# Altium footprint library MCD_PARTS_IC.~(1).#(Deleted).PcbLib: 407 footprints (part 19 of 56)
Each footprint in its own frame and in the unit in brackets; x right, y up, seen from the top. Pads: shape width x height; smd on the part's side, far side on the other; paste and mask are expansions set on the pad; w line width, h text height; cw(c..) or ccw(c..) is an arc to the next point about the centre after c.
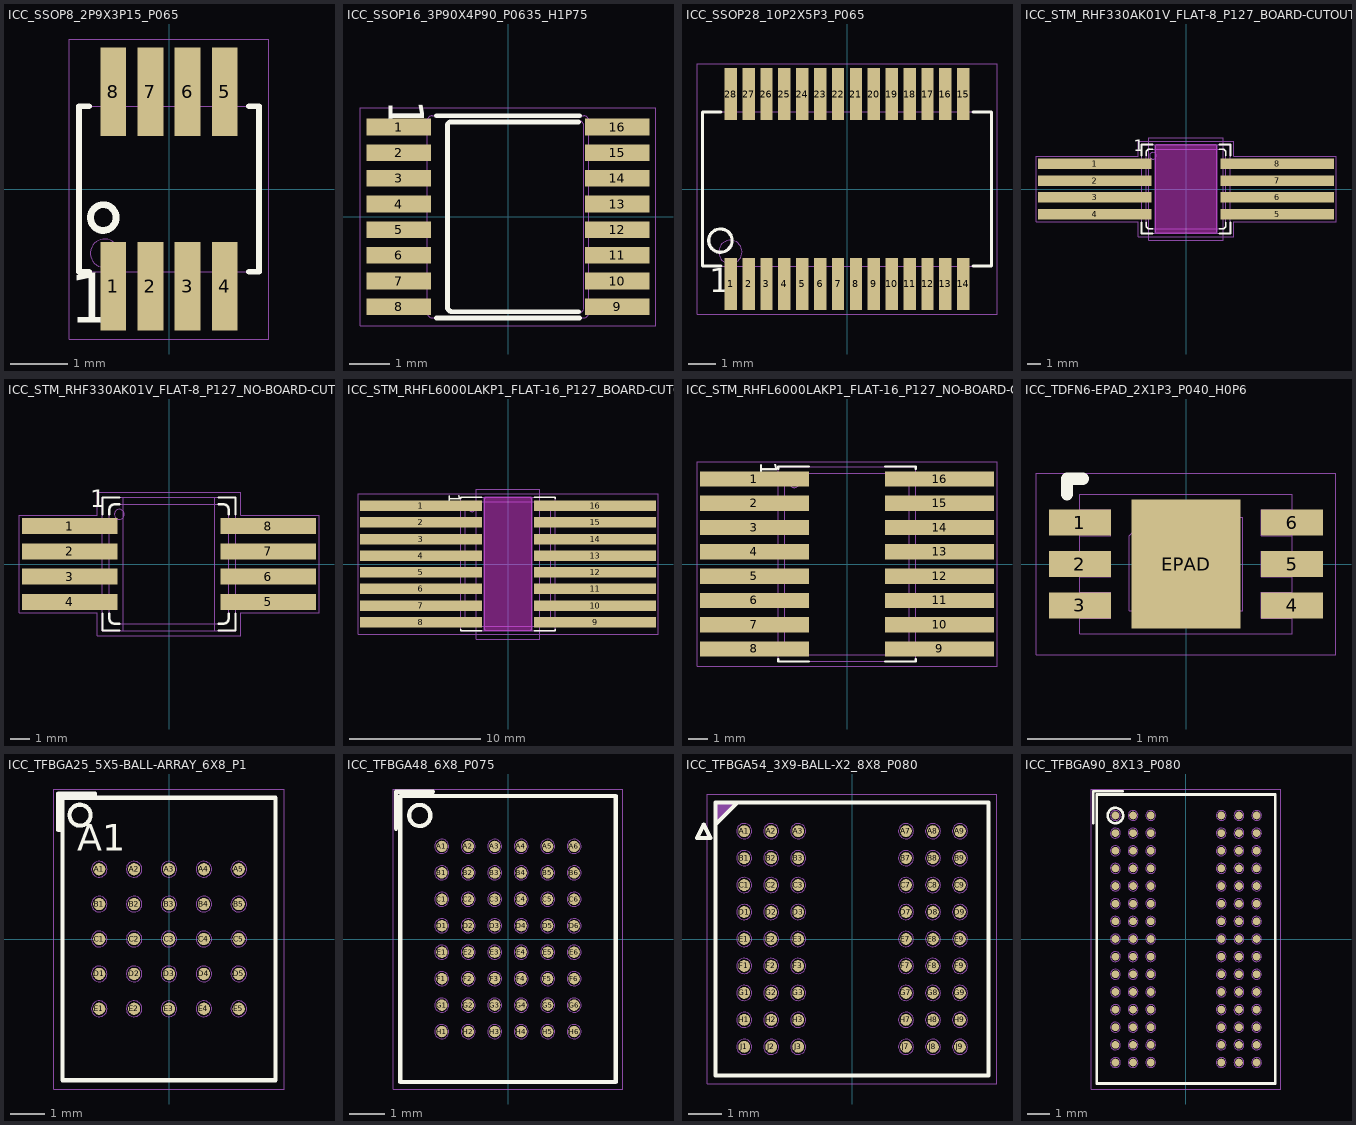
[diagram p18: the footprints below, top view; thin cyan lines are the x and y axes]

## ICC_SSOP8_2P9X3P15_P065 [mm] "MCD-02193"
height 1.3
pads (8):
  rect 0.45x1.55 smd mask+0.05: 1(-0.975,-1.7) 2(-0.325,-1.7) 3(0.325,-1.7) 4(0.975,-1.7) 5(0.975,1.7) 6(0.325,1.7) 7(-0.325,1.7) 8(-0.975,1.7)
Top Overlay:
  circle w0.12: c-1.15,-0.5 r0.225
  lines w0.1: -1.4,-1.45 -1.575,-1.45 -1.575,1.45 -1.4,1.45 ; 1.4,-1.45 1.575,-1.45 1.575,1.45 1.4,1.45
  text "1" at -1.75,-2.625 h1.5
M14-Top Assembly:
  circle w0.01: c-1.125,-1.125 r0.25
  lines w0.01: -1.125,-1.45 -1.125,-2.125 -0.825,-2.125 -0.825,-1.45 ; -1.125,1.45 -1.125,2.125 -0.825,2.125 -0.825,1.45 ; -0.475,-1.45 -0.475,-2.125 -0.175,-2.125 -0.175,-1.45 ; -0.475,1.45 -0.475,2.125 -0.175,2.125 -0.175,1.45 ; 0.175,-1.45 0.175,-2.125 0.475,-2.125 0.475,-1.45 ; 0.175,1.45 0.175,2.125 0.475,2.125 0.475,1.45 ; 0.825,-1.45 0.825,-2.125 1.125,-2.125 1.125,-1.45 ; 0.825,1.45 0.825,2.125 1.125,2.125 1.125,1.45 ; -1.575,-1.45 -1.575,1.45 1.575,1.45 1.575,-1.45 -1.575,-1.45
  text "1" at -1.1,-2.4 h1
  text "4" at 0.75,-2.375 h1
  text "8" at -1.2,1.725 h1
  text "5" at 0.775,1.725 h1
  text "'.Designator'" at -2,-0.5 h0.75
M16-Top Courtyard:
  lines w0.01: -1.75,-2.625 -1.75,2.625 1.75,2.625 1.75,-2.625 -1.75,-2.625
3D body: height 1.11, standoff 1.1, extent -1.373,-1.374 -0.875,-0.875
3D body: height 1.1, standoff 0, extent -1.575,-1.45 1.575,1.45
3D body "User Library-SSOP-8-1.STEP": height 1.28, standoff -0.02, extent -1.587,-2.173 1.563,2.077

## ICC_SSOP16_3P90X4P90_P0635_H1P75 [mm]
height 1.75
pads (16):
  rect 1.6x0.41 smd mask+0.05: 1(-2.7,2.222) 2(-2.7,1.587) 3(-2.7,0.953) 4(-2.7,0.318) 5(-2.7,-0.318) 6(-2.7,-0.953) 7(-2.7,-1.587) 8(-2.7,-2.222) 9(2.7,-2.222) 10(2.7,-1.587) 11(2.7,-0.953) 12(2.7,-0.318) 13(2.7,0.318) 14(2.7,0.953) 15(2.7,1.587) 16(2.7,2.222)
Top Overlay:
  lines w0.12: -1.775,-2.5 1.775,-2.5 ; -1.775,2.5 1.775,2.5 ; 1.75,-2.35 -1.375,-2.35 cw(c-1.375,-2.225) -1.5,-2.225 -1.5,2.25 cw(c-1.4,2.25) -1.4,2.35 1.75,2.35
  text "1" at -3.25,2.9 h1.5
M14-Top Assembly:
  lines w0.01: -2,-2.372 -3.1,-2.372 -3.1,-2.073 -2,-2.073 ; -2,-1.737 -3.1,-1.737 -3.1,-1.438 -2,-1.438 ; -2,-1.102 -3.1,-1.102 -3.1,-0.803 -2,-0.803 ; -2,-0.467 -3.1,-0.467 -3.1,-0.168 -2,-0.168 ; -2,0.168 -3.1,0.168 -3.1,0.467 -2,0.467 ; -2,0.803 -3.1,0.803 -3.1,1.102 -2,1.102 ; -2,1.438 -3.1,1.438 -3.1,1.737 -2,1.737 ; -2,2.073 -3.1,2.073 -3.1,2.372 -2,2.372 ; 2,-2.372 3.1,-2.372 3.1,-2.073 2,-2.073 ; 2,-1.737 3.1,-1.737 3.1,-1.438 2,-1.438 ; 2,-1.102 3.1,-1.102 3.1,-0.803 2,-0.803 ; 2,-0.467 3.1,-0.467 3.1,-0.168 2,-0.168 ; 2,0.168 3.1,0.168 3.1,0.467 2,0.467 ; 2,0.803 3.1,0.803 3.1,1.102 2,1.102 ; 2,1.438 3.1,1.438 3.1,1.737 2,1.737 ; 2,2.073 3.1,2.073 3.1,2.372 2,2.372 ; -2,-2.375 ccw(c-1.875,-2.375) -1.875,-2.5 1.875,-2.5 ccw(c1.875,-2.375) 2,-2.375 2,2.375 ccw(c1.875,2.375) 1.875,2.5 -1.875,2.5 ccw(c-1.875,2.375) -2,2.375 -2,-2.375 ; -1.5,-2.25 ccw(c-1.375,-2.25) -1.375,-2.375 1.75,-2.375 ccw(c1.75,-2.25) 1.875,-2.25 1.875,2.25 ccw(c1.75,2.25) 1.75,2.375 -1.375,2.375 ccw(c-1.375,2.25) -1.5,2.25 -1.5,-2.25
  text "'.Designator'" at -2,-0.5 h0.75
  text "1" at -2.65,2 h0.75
  text "8" at -2.675,-2.475 h0.75
  text "9" at 2.375,-2.475 h0.75
  text "16" at 2.225,2 h0.75
M16-Top Courtyard:
  lines w0.01: -3.65,-2.7 -3.65,2.7 3.65,2.7 3.65,-2.7 -3.65,-2.7
3D body: height 1.75, standoff 0, extent -2,-2.5 2,2.5
3D body "SSOP16_5X4_P0635.STEP": height 1.1, standoff 0, extent -2.997,-2.538 2.997,2.44
3D body: height 1.11, standoff 1.1, extent -1.323,1.801 -0.925,2.2

## ICC_SSOP28_10P2X5P3_P065 [mm]
height 2
pads (28):
  rect 0.45x1.9 smd mask+0.05: 1(-4.225,-3.45) 2(-3.575,-3.45) 3(-2.925,-3.45) 4(-2.275,-3.45) 5(-1.625,-3.45) 6(-0.975,-3.45) 7(-0.325,-3.45) 8(0.325,-3.45) 9(0.975,-3.45) 10(1.625,-3.45) 11(2.275,-3.45) 12(2.925,-3.45) 13(3.575,-3.45) 14(4.225,-3.45) 15(4.225,3.45) 16(3.575,3.45) 17(2.925,3.45) 18(2.275,3.45) 19(1.625,3.45) 20(0.975,3.45) 21(0.325,3.45) 22(-0.325,3.45) 23(-0.975,3.45) 24(-1.625,3.45) 25(-2.275,3.45) 26(-2.925,3.45) 27(-3.575,3.45) 28(-4.225,3.45)
Top Overlay:
  circle w0.12: c-4.6,-1.875 r0.425
  lines w0.12: -4.575,-2.8 -5.25,-2.8 -5.25,2.8 -4.575,2.8 ; 4.575,-2.8 5.25,-2.8 5.25,2.8 4.575,2.8
  text "1" at -5,-4.05 h1.5
M14-Top Assembly:
  circle w0.01: c-4.238,-2.288 r0.425
  lines w0.01: -4.387,-2.8 -4.387,-4.1 -4.062,-4.1 -4.062,-2.8 ; -4.387,2.8 -4.387,4.1 -4.062,4.1 -4.062,2.8 ; -3.738,-2.8 -3.738,-4.1 -3.413,-4.1 -3.413,-2.8 ; -3.738,2.8 -3.738,4.1 -3.413,4.1 -3.413,2.8 ; -3.087,-2.8 -3.087,-4.1 -2.762,-4.1 -2.762,-2.8 ; -3.087,2.8 -3.087,4.1 -2.762,4.1 -2.762,2.8 ; -2.438,-2.8 -2.438,-4.1 -2.113,-4.1 -2.113,-2.8 ; -2.438,2.8 -2.438,4.1 -2.113,4.1 -2.113,2.8 ; -1.787,-2.8 -1.787,-4.1 -1.462,-4.1 -1.462,-2.8 ; -1.787,2.8 -1.787,4.1 -1.462,4.1 -1.462,2.8 ; -1.138,-2.8 -1.138,-4.1 -0.813,-4.1 -0.813,-2.8 ; -1.138,2.8 -1.138,4.1 -0.813,4.1 -0.813,2.8 ; -0.487,-2.8 -0.487,-4.1 -0.162,-4.1 -0.162,-2.8 ; -0.487,2.8 -0.487,4.1 -0.162,4.1 -0.162,2.8 ; 0.162,-2.8 0.162,-4.1 0.487,-4.1 0.487,-2.8 ; 0.162,2.8 0.162,4.1 0.487,4.1 0.487,2.8 ; 0.813,-2.8 0.813,-4.1 1.138,-4.1 1.138,-2.8 ; 0.813,2.8 0.813,4.1 1.138,4.1 1.138,2.8 ; 1.462,-2.8 1.462,-4.1 1.787,-4.1 1.787,-2.8 ; 1.462,2.8 1.462,4.1 1.787,4.1 1.787,2.8 ; 2.113,-2.8 2.113,-4.1 2.438,-4.1 2.438,-2.8 ; 2.113,2.8 2.113,4.1 2.438,4.1 2.438,2.8 ; 2.762,-2.8 2.762,-4.1 3.087,-4.1 3.087,-2.8 ; 2.762,2.8 2.762,4.1 3.087,4.1 3.087,2.8 ; 3.413,-2.8 3.413,-4.1 3.738,-4.1 3.738,-2.8 ; 3.413,2.8 3.413,4.1 3.738,4.1 3.738,2.8 ; 4.062,-2.8 4.062,-4.1 4.387,-4.1 4.387,-2.8 ; 4.062,2.8 4.062,4.1 4.387,4.1 4.387,2.8 ; -5.25,-2.8 -5.25,2.8 5.25,2.8 5.25,-2.8 -5.25,-2.8
  text "'.Designator'" at -2,-0.5 h0.75
  text "1" at -4.363,-3.638 h1
  text "14" at 3.825,-3.75 h1
  text "15" at 3.762,2.987 h1
  text "28" at -4.688,2.987 h1
M16-Top Courtyard:
  lines w0.01: -5.45,-4.55 -5.45,4.55 5.45,4.55 5.45,-4.55 -5.45,-4.55
3D body "SSOP28_10P2X5P3_P065.STEP": height 1.9, standoff 0, extent -5.1,-3.9 5.1,3.9
3D body: height 2, standoff 0, extent -5.249,-2.799 5.249,2.799

## ICC_STM_RHF330AK01V_FLAT-8_P127_BOARD-CUTOUT_LONG-PIN [mm]
height 1.72
pads (8):
  rect 8.55x0.8 smd mask+0.038: 1(-6.875,1.905) 2(-6.875,0.635) 3(-6.875,-0.635) 4(-6.875,-1.905) 5(6.875,-1.905) 6(6.875,-0.635) 7(6.875,0.635) 8(6.875,1.905)
Top Overlay:
  lines w0.12: -3.35,-2.5 -3.35,-3.35 -2.5,-3.35 ; -3.35,2.5 -3.35,3.35 -2.5,3.35 ; -3,-2.5 -3,-2.75 ccw(c-2.75,-2.75) -2.75,-3 -2.5,-3 ; -3,2.5 -3,2.75 cw(c-2.75,2.75) -2.75,3 -2.5,3 ; 2.5,-3.35 3.35,-3.35 3.35,-2.5 ; 2.5,-3 2.75,-3 ccw(c2.75,-2.75) 3,-2.75 3,-2.5 ; 2.5,3 2.75,3 cw(c2.75,2.75) 3,2.75 3,2.5 ; 2.5,3.35 3.35,3.35 3.35,2.5
  text "1" at -3.954,2.543 h1.5
Keep-Out Layer:
  board cut-out: -2.2,3.35 -2.22,3.35 -2.257,3.335 -2.285,3.307 -2.3,3.27 -2.3,3.25 -2.3,-3.25 -2.3,-3.27 -2.285,-3.307 -2.257,-3.335 -2.22,-3.35 -2.2,-3.35 2.2,-3.35 2.22,-3.35 2.257,-3.335 2.285,-3.307 2.3,-3.27 2.3,-3.25 2.3,3.25 2.3,3.27 2.285,3.307 2.257,3.335 2.22,3.35 2.2,3.35
M1-Board Shape:
  lines w0.1: -2.3,-3.25 ccw(c-2.2,-3.25) -2.2,-3.35 2.2,-3.35 ccw(c2.2,-3.25) 2.3,-3.25 2.3,3.25 ccw(c2.2,3.25) 2.2,3.35 -2.2,3.35 ccw(c-2.2,3.25) -2.3,3.25 -2.3,-3.25
M14-Top Assembly:
  circle w0.01: c-2.5,2.5 r0.25
  lines w0.01: -3.35,-2.155 -10.75,-2.155 -10.75,-1.655 -3.35,-1.655 ; -3.35,-0.885 -10.75,-0.885 -10.75,-0.385 -3.35,-0.385 ; -3.35,0.385 -10.75,0.385 -10.75,0.885 -3.35,0.885 ; -3.35,1.655 -10.75,1.655 -10.75,2.155 -3.35,2.155 ; 3.35,-2.155 10.75,-2.155 10.75,-1.655 3.35,-1.655 ; 3.35,-0.885 10.75,-0.885 10.75,-0.385 3.35,-0.385 ; 3.35,0.385 10.75,0.385 10.75,0.885 3.35,0.885 ; 3.35,1.655 10.75,1.655 10.75,2.155 3.35,2.155 ; -3.35,-3.35 3.35,-3.35 3.35,3.35 -3.35,3.35 -3.35,-3.35 ; -3,-2.75 ccw(c-2.75,-2.75) -2.75,-3 2.75,-3 ccw(c2.75,-2.75) 3,-2.75 3,2.75 ccw(c2.75,2.75) 2.75,3 -2.75,3 ccw(c-2.75,2.75) -3,2.75 -3,-2.75
  text "8" at 3.5,1.431 h1.5
  text "5" at 3.5,-2.37 h1.5
  text "4" at -4.166,-2.385 h1.5
  text "1" at -3.854,1.423 h1.5
  text "'.Designator'" at -2,-0.5 h0.75
M15-Bottom Assembly:
  lines w0.01: 2.3,-3.35 ccw(c2.3,-3.35) 2.3,-3.35 ; 2.3,-3.35 2.3,3.35 -2.3,3.35 -2.3,-3.35 2.3,-3.35
M16-Top Courtyard:
  lines w0.01: -11.3,-2.45 -3.6,-2.45 -3.6,-3.6 3.6,-3.6 3.6,-2.45 11.3,-2.45 11.3,2.45 3.6,2.45 3.6,3.6 -3.6,3.6 -3.6,2.45 -11.3,2.45 -11.3,-2.45
M17-Bottom Courtyard:
  lines w0.01: -2.8,-3.85 2.8,-3.85 2.8,3.85 -2.8,3.85 -2.8,-3.85
3D body: height 0.16, standoff -0.92, extent -2.25,-3.3 2.25,3.3
3D body: height 1.36, standoff 0.16, extent -3.35,-3.35 3.35,3.35
3D body: height 1.72, standoff 1.36, extent -3,-3 3,3
3D body: height 1.73, standoff 1.72, extent -2.75,2.25 -2.25,2.75
3D body: height 1.36, standoff 0.16, extent -3.375,1.655 -3.35,2.155
3D body: height 0.16, standoff 0, extent -10.75,1.655 -2.6,2.155
3D body: height 1.36, standoff 0.16, extent 3.35,-2.155 3.375,-1.655
3D body: height 1.36, standoff 0.16, extent 3.35,-0.885 3.375,-0.385
3D body: height 0.16, standoff 0, extent 2.6,0.385 10.75,0.885
3D body: height 1.36, standoff 0.16, extent 3.35,0.385 3.375,0.885
3D body: height 0.16, standoff 0, extent 2.6,1.655 10.75,2.155
3D body: height 1.36, standoff 0.16, extent 3.35,1.655 3.375,2.155
3D body: height 0.16, standoff 0, extent 2.6,-2.155 10.75,-1.655
3D body: height 0.16, standoff 0, extent 2.6,-0.885 10.75,-0.385
3D body: height 0.16, standoff 0, extent -10.75,0.385 -2.6,0.885
3D body: height 1.36, standoff 0.16, extent -3.375,0.385 -3.35,0.885
3D body: height 0.16, standoff 0, extent -10.75,-0.885 -2.6,-0.385
3D body: height 1.36, standoff 0.16, extent -3.375,-0.885 -3.35,-0.385
3D body: height 0.16, standoff 0, extent -10.75,-2.155 -2.6,-1.655
3D body: height 1.36, standoff 0.16, extent -3.375,-2.155 -3.35,-1.655

## ICC_STM_RHF330AK01V_FLAT-8_P127_NO-BOARD-CUTOUT_SHORT-PIN [mm] "MCD-03681"
height 2.64
pads (8):
  rect 4.8x0.8 smd mask+0.038: 1(-5,1.905) 2(-5,0.635) 3(-5,-0.635) 4(-5,-1.905) 5(5,-1.905) 6(5,-0.635) 7(5,0.635) 8(5,1.905)
Top Overlay:
  lines w0.12: -3.35,-2.5 -3.35,-3.35 -2.5,-3.35 ; -3.35,2.5 -3.35,3.35 -2.5,3.35 ; -3,-2.5 -3,-2.75 ccw(c-2.75,-2.75) -2.75,-3 -2.5,-3 ; -3,2.5 -3,2.75 cw(c-2.75,2.75) -2.75,3 -2.5,3 ; 2.5,-3.35 3.35,-3.35 3.35,-2.5 ; 2.5,-3 2.75,-3 ccw(c2.75,-2.75) 3,-2.75 3,-2.5 ; 2.5,3 2.75,3 cw(c2.75,2.75) 3,2.75 3,2.5 ; 2.5,3.35 3.35,3.35 3.35,2.5
  text "1" at -3.954,2.543 h1.5
M14-Top Assembly:
  circle w0.01: c-2.5,2.5 r0.25
  lines w0.01: -5.5,-2.155 -5.5,-1.655 ; -5.5,-0.885 -5.5,-0.385 ; -5.5,0.385 -5.5,0.885 ; -5.5,1.655 -5.5,2.155 ; -5.35,-2.155 -5.35,-1.655 ; -5.35,-0.885 -5.35,-0.385 ; -5.35,0.385 -5.35,0.885 ; -5.35,1.655 -5.35,2.155 ; -3.35,-2.155 -7,-2.155 -7,-1.655 -3.35,-1.655 ; -3.35,-0.885 -7,-0.885 -7,-0.385 -3.35,-0.385 ; -3.35,0.385 -7,0.385 -7,0.885 -3.35,0.885 ; -3.35,1.655 -7,1.655 -7,2.155 -3.35,2.155 ; 3.35,-2.155 7,-2.155 7,-1.655 3.35,-1.655 ; 3.35,-0.885 7,-0.885 7,-0.385 3.35,-0.385 ; 3.35,0.385 7,0.385 7,0.885 3.35,0.885 ; 3.35,1.655 7,1.655 7,2.155 3.35,2.155 ; 5.35,-2.155 5.35,-1.655 ; 5.35,-0.885 5.35,-0.385 ; 5.35,0.385 5.35,0.885 ; 5.35,1.655 5.35,2.155 ; 5.5,-2.155 5.5,-1.655 ; 5.5,-0.885 5.5,-0.385 ; 5.5,0.385 5.5,0.885 ; 5.5,1.655 5.5,2.155 ; 2.3,-3.35 ccw(c2.3,-3.35) 2.3,-3.35 ; 2.3,-3.35 -2.3,-3.35 -2.3,3.35 2.3,3.35 2.3,-3.35 ; -3.35,-3.35 -3.35,3.35 3.35,3.35 3.35,-3.35 -3.35,-3.35 ; -3,-2.75 ccw(c-2.75,-2.75) -2.75,-3 2.75,-3 ccw(c2.75,-2.75) 3,-2.75 3,2.75 ccw(c2.75,2.75) 2.75,3 -2.75,3 ccw(c-2.75,2.75) -3,2.75 -3,-2.75
  text "'.Designator'" at -2,-0.5 h0.75
  text "1" at -3.854,1.423 h1.5
  text "4" at -4.166,-2.385 h1.5
  text "5" at 3.5,-2.37 h1.5
  text "8" at 3.5,1.431 h1.5
M16-Top Courtyard:
  lines w0.01: -7.55,-2.45 -3.6,-2.45 -3.6,-3.6 3.6,-3.6 3.6,-2.45 7.55,-2.45 7.55,2.45 3.6,2.45 3.6,3.6 -3.6,3.6 -3.6,2.45 -7.55,2.45 -7.55,-2.45
3D body: height 0.16, standoff 0, extent -7,1.655 -5.35,2.155
3D body: height 1.08, standoff 0, extent -5.5,1.655 -5.35,2.155
3D body: height 0.16, standoff 0, extent -7,0.385 -5.35,0.885
3D body: height 1.08, standoff 0, extent -5.5,0.385 -5.35,0.885
3D body: height 0.16, standoff 0, extent -7,-0.885 -5.35,-0.385
3D body: height 1.08, standoff 0, extent -5.5,-0.885 -5.35,-0.385
3D body: height 0.16, standoff 0, extent -7,-2.155 -5.35,-1.655
3D body: height 1.08, standoff 0, extent -5.5,-2.155 -5.35,-1.655
3D body: height 1.08, standoff 0.92, extent -5.5,1.655 -2.6,2.155
3D body: height 1.08, standoff 0.92, extent -5.5,0.385 -2.6,0.885
3D body: height 1.08, standoff 0.92, extent -5.5,-0.885 -2.6,-0.385
3D body: height 1.08, standoff 0.92, extent -5.5,-2.155 -2.6,-1.655
3D body: height 0.16, standoff 0, extent 5.35,1.655 7,2.155
3D body: height 1.08, standoff 0, extent 5.35,1.655 5.5,2.155
3D body: height 0.16, standoff 0, extent 5.35,-0.885 7,-0.385
3D body: height 1.08, standoff 0, extent 5.35,-0.885 5.5,-0.385
3D body: height 0.16, standoff 0, extent 5.35,0.385 7,0.885
3D body: height 1.08, standoff 0, extent 5.35,0.385 5.5,0.885
3D body: height 0.16, standoff 0, extent 5.35,-2.155 7,-1.655
3D body: height 1.08, standoff 0, extent 5.35,-2.155 5.5,-1.655
3D body: height 1.08, standoff 0.92, extent 2.6,1.655 5.5,2.155
3D body: height 1.08, standoff 0.92, extent 2.6,0.385 5.5,0.885
3D body: height 1.08, standoff 0.92, extent 2.6,-0.885 5.5,-0.385
3D body: height 1.08, standoff 0.92, extent 2.6,-2.155 5.5,-1.655
3D body: height 1.08, standoff 0, extent -2.25,-3.3 2.25,3.3
3D body: height 2.28, standoff 1.08, extent -3.35,-3.35 3.35,3.35
3D body: height 2.64, standoff 2.28, extent -3,-3 3,3
3D body: height 2.65, standoff 2.64, extent -2.75,2.25 -2.25,2.75
3D body: height 2.28, standoff 1.08, extent -3.375,-2.155 -3.35,-1.655
3D body: height 2.28, standoff 1.08, extent -3.375,-0.885 -3.35,-0.385
3D body: height 2.28, standoff 1.08, extent -3.375,0.385 -3.35,0.885
3D body: height 2.28, standoff 1.08, extent -3.375,1.655 -3.35,2.155
3D body: height 2.28, standoff 1.08, extent 3.35,1.655 3.375,2.155
3D body: height 2.28, standoff 1.08, extent 3.35,-0.885 3.375,-0.385
3D body: height 2.28, standoff 1.08, extent 3.35,0.385 3.375,0.885
3D body: height 2.28, standoff 1.08, extent 3.35,-2.155 3.375,-1.655

## ICC_STM_RHFL6000LAKP1_FLAT-16_P127_BOARD-CUTOUT_LONG-PIN [mm] "MCD-03708"
height 1.74
pads (16):
  rect 9.3x0.8 smd mask+0.038: 1(-6.65,4.445) 2(-6.65,3.175) 3(-6.65,1.905) 4(-6.65,0.635) 5(-6.65,-0.635) 6(-6.65,-1.905) 7(-6.65,-3.175) 8(-6.65,-4.445) 9(6.65,-4.445) 10(6.65,-3.175) 11(6.65,-1.905) 12(6.65,-0.635) 13(6.65,0.635) 14(6.65,1.905) 15(6.65,3.175) 16(6.65,4.445)
Top Overlay:
  lines w0.12: -3.6,-4.975 -3.6,-5.1 -2,-5.1 ; -3.6,4.975 -3.6,5.1 -2,5.1 ; 2,-5.1 3.6,-5.1 3.6,-4.975 ; 2,5.1 3.6,5.1 3.6,4.975
  text "1" at -4.832,5.354 h1.5
Keep-Out Layer:
  board cut-out: -1.7,5.1 -1.72,5.1 -1.757,5.085 -1.785,5.057 -1.8,5.02 -1.8,5 -1.8,-5 -1.8,-5.02 -1.785,-5.057 -1.757,-5.085 -1.72,-5.1 -1.7,-5.1 1.7,-5.1 1.72,-5.1 1.757,-5.085 1.785,-5.057 1.8,-5.02 1.8,-5 1.8,5 1.8,5.02 1.785,5.057 1.757,5.085 1.72,5.1 1.7,5.1
M1-Board Shape:
  lines w0.1: -1.8,-5 ccw(c-1.7,-5) -1.7,-5.1 1.7,-5.1 ccw(c1.7,-5) 1.8,-5 1.8,5 ccw(c1.7,5) 1.7,5.1 -1.7,5.1 ccw(c-1.7,5) -1.8,5 -1.8,-5
M14-Top Assembly:
  circle w0.01: c-2.75,4.25 r0.25
  lines w0.01: -3.6,-4.695 -11,-4.695 -11,-4.195 -3.6,-4.195 ; -3.6,-3.425 -11,-3.425 -11,-2.925 -3.6,-2.925 ; -3.6,-2.155 -11,-2.155 -11,-1.655 -3.6,-1.655 ; -3.6,-0.885 -11,-0.885 -11,-0.385 -3.6,-0.385 ; -3.6,0.385 -11,0.385 -11,0.885 -3.6,0.885 ; -3.6,1.655 -11,1.655 -11,2.155 -3.6,2.155 ; -3.6,2.925 -11,2.925 -11,3.425 -3.6,3.425 ; -3.6,4.195 -11,4.195 -11,4.695 -3.6,4.695 ; 3.6,-4.695 11,-4.695 11,-4.195 3.6,-4.195 ; 3.6,-3.425 11,-3.425 11,-2.925 3.6,-2.925 ; 3.6,-2.155 11,-2.155 11,-1.655 3.6,-1.655 ; 3.6,-0.885 11,-0.885 11,-0.385 3.6,-0.385 ; 3.6,0.385 11,0.385 11,0.885 3.6,0.885 ; 3.6,1.655 11,1.655 11,2.155 3.6,2.155 ; 3.6,2.925 11,2.925 11,3.425 3.6,3.425 ; 3.6,4.195 11,4.195 11,4.695 3.6,4.695 ; -3.6,-5.1 -3.6,5.1 3.6,5.1 3.6,-5.1 -3.6,-5.1 ; -3.25,-4.5 ccw(c-3,-4.5) -3,-4.75 3,-4.75 ccw(c3,-4.5) 3.25,-4.5 3.25,4.5 ccw(c3,4.5) 3,4.75 -3,4.75 ccw(c-3,4.5) -3.25,4.5 -3.25,-4.5
  text "'.Designator'" at -2,-0.5 h0.75
  text "1" at -4.154,3.963 h1.5
  text "8" at -4.432,-4.919 h1.5
  text "9" at 3.8,-4.919 h1.5
  text "16" at 3.8,3.971 h1.5
M15-Bottom Assembly:
  lines w0.01: -1.8,-5.1 -1.8,5.1 1.8,5.1 1.8,-5.1 -1.8,-5.1
M16-Top Courtyard:
  lines w0.01: -11.45,-5.35 -11.45,5.35 11.45,5.35 11.45,-5.35 -11.45,-5.35
M17-Bottom Courtyard:
  lines w0.01: -2.425,-5.725 -2.425,5.725 2.425,5.725 2.425,-5.725 -2.425,-5.725
3D body: height 0.18, standoff -1.14, extent -1.8,-5.1 1.8,5.1
3D body: height 1.74, standoff 1.38, extent -3.25,-4.75 3.25,4.75
3D body: height 1.75, standoff 1.74, extent -3,4 -2.5,4.5
3D body: height 0.18, standoff 0, extent 2,2.925 11,3.425
3D body: height 0.18, standoff 0, extent 2,-3.425 11,-2.925
3D body: height 1.38, standoff 0.18, extent -3.6,-5.1 3.6,5.1
3D body: height 1.38, standoff 0.18, extent 3.6,-4.695 3.625,-4.195
3D body: height 1.38, standoff 0.18, extent 3.6,-3.425 3.625,-2.925
3D body: height 1.38, standoff 0.18, extent 3.6,-2.155 3.625,-1.655
3D body: height 0.18, standoff 0, extent 2,-0.885 11,-0.385
3D body: height 0.18, standoff 0, extent 2,-2.155 11,-1.655
3D body: height 1.38, standoff 0.18, extent 3.6,0.385 3.625,0.885
3D body: height 1.38, standoff 0.18, extent 3.6,1.655 3.625,2.155
3D body: height 1.38, standoff 0.18, extent 3.6,2.925 3.625,3.425
3D body: height 1.38, standoff 0.18, extent 3.6,4.195 3.625,4.695
3D body: height 1.38, standoff 0.18, extent 3.6,-0.885 3.625,-0.385
3D body: height 0.18, standoff 0, extent 2,0.385 11,0.885
3D body: height 0.18, standoff 0, extent 2,1.655 11,2.155
3D body: height 0.18, standoff 0, extent 2,4.195 11,4.695
3D body: height 0.18, standoff 0, extent 2,-4.695 11,-4.195
3D body: height 1.38, standoff 0.18, extent -3.625,4.195 -3.6,4.695
3D body: height 0.18, standoff 0, extent -11,4.195 -2,4.695
3D body: height 1.38, standoff 0.18, extent -3.625,2.925 -3.6,3.425
3D body: height 0.18, standoff 0, extent -11,2.925 -2,3.425
3D body: height 1.38, standoff 0.18, extent -3.625,1.655 -3.6,2.155
3D body: height 0.18, standoff 0, extent -11,1.655 -2,2.155
3D body: height 1.38, standoff 0.18, extent -3.625,0.385 -3.6,0.885
3D body: height 0.18, standoff 0, extent -11,0.385 -2,0.885
3D body: height 1.38, standoff 0.18, extent -3.625,-0.885 -3.6,-0.385
3D body: height 0.18, standoff 0, extent -11,-0.885 -2,-0.385
3D body: height 1.38, standoff 0.18, extent -3.625,-2.155 -3.6,-1.655
3D body: height 0.18, standoff 0, extent -11,-2.155 -2,-1.655
3D body: height 1.38, standoff 0.18, extent -3.625,-3.425 -3.6,-2.925
3D body: height 0.18, standoff 0, extent -11,-3.425 -2,-2.925
3D body: height 1.38, standoff 0.18, extent -3.625,-4.695 -3.6,-4.195
3D body: height 0.18, standoff 0, extent -11,-4.695 -2,-4.195

## ICC_STM_RHFL6000LAKP1_FLAT-16_P127_NO-BOARD-CUTOUT_SHORT-PIN [mm] "MCD-03708"
height 2.88
pads (16):
  rect 5.7x0.8 smd mask+0.038: 1(-4.85,4.445) 2(-4.85,3.175) 3(-4.85,1.905) 4(-4.85,0.635) 5(-4.85,-0.635) 6(-4.85,-1.905) 7(-4.85,-3.175) 8(-4.85,-4.445) 9(4.85,-4.445) 10(4.85,-3.175) 11(4.85,-1.905) 12(4.85,-0.635) 13(4.85,0.635) 14(4.85,1.905) 15(4.85,3.175) 16(4.85,4.445)
Top Overlay:
  lines w0.12: -3.6,-4.975 -3.6,-5.1 -2,-5.1 ; -3.6,4.975 -3.6,5.1 -2,5.1 ; 2,-5.1 3.6,-5.1 3.6,-4.975 ; 2,5.1 3.6,5.1 3.6,4.975
  text "1" at -4.832,5.354 h1.5
M14-Top Assembly:
  circle w0.01: c-2.75,4.25 r0.25
  lines w0.01: -5.8,-4.7 -5.8,-4.2 ; -5.8,-3.43 -5.8,-2.93 ; -5.8,-2.16 -5.8,-1.66 ; -5.8,-0.89 -5.8,-0.39 ; -5.8,0.38 -5.8,0.88 ; -5.8,1.65 -5.8,2.15 ; -5.8,2.92 -5.8,3.42 ; -5.8,4.19 -5.8,4.69 ; -5.6,-4.7 -5.6,-4.2 ; -5.6,-3.43 -5.6,-2.93 ; -5.6,-2.16 -5.6,-1.66 ; -5.6,-0.89 -5.6,-0.39 ; -5.6,0.38 -5.6,0.88 ; -5.6,1.65 -5.6,2.15 ; -5.6,2.92 -5.6,3.42 ; -5.6,4.19 -5.6,4.69 ; -3.6,-4.695 -7.4,-4.695 -7.4,-4.195 -3.6,-4.195 ; -3.6,-3.425 -7.4,-3.425 -7.4,-2.925 -3.6,-2.925 ; -3.6,-2.155 -7.4,-2.155 -7.4,-1.655 -3.6,-1.655 ; -3.6,-0.885 -7.4,-0.885 -7.4,-0.385 -3.6,-0.385 ; -3.6,0.385 -7.4,0.385 -7.4,0.885 -3.6,0.885 ; -3.6,1.655 -7.4,1.655 -7.4,2.155 -3.6,2.155 ; -3.6,2.925 -7.4,2.925 -7.4,3.425 -3.6,3.425 ; -3.6,4.195 -7.4,4.195 -7.4,4.695 -3.6,4.695 ; 3.6,-4.695 7.4,-4.695 7.4,-4.195 3.6,-4.195 ; 3.6,-3.425 7.4,-3.425 7.4,-2.925 3.6,-2.925 ; 3.6,-2.155 7.4,-2.155 7.4,-1.655 3.6,-1.655 ; 3.6,-0.885 7.4,-0.885 7.4,-0.385 3.6,-0.385 ; 3.6,0.385 7.4,0.385 7.4,0.885 3.6,0.885 ; 3.6,1.655 7.4,1.655 7.4,2.155 3.6,2.155 ; 3.6,2.925 7.4,2.925 7.4,3.425 3.6,3.425 ; 3.6,4.195 7.4,4.195 7.4,4.695 3.6,4.695 ; 5.6,-4.69 5.6,-4.19 ; 5.6,-3.42 5.6,-2.92 ; 5.6,-2.15 5.6,-1.65 ; 5.6,-0.88 5.6,-0.38 ; 5.6,0.39 5.6,0.89 ; 5.6,1.66 5.6,2.16 ; 5.6,2.93 5.6,3.43 ; 5.6,4.2 5.6,4.7 ; 5.8,-4.69 5.8,-4.19 ; 5.8,-3.42 5.8,-2.92 ; 5.8,-2.15 5.8,-1.65 ; 5.8,-0.88 5.8,-0.38 ; 5.8,0.39 5.8,0.89 ; 5.8,1.66 5.8,2.16 ; 5.8,2.93 5.8,3.43 ; 5.8,4.2 5.8,4.7 ; -3.6,-5.1 3.6,-5.1 3.6,5.1 -3.6,5.1 -3.6,-5.1 ; -3.25,-4.5 ccw(c-3,-4.5) -3,-4.75 3,-4.75 ccw(c3,-4.5) 3.25,-4.5 3.25,4.5 ccw(c3,4.5) 3,4.75 -3,4.75 ccw(c-3,4.5) -3.25,4.5 -3.25,-4.5
  text "16" at 3.8,3.971 h1.5
  text "9" at 3.8,-4.919 h1.5
  text "8" at -4.432,-4.919 h1.5
  text "1" at -4.154,3.963 h1.5
  text "'.Designator'" at -2,-0.5 h0.75
M16-Top Courtyard:
  lines w0.01: -7.85,-5.35 7.85,-5.35 7.85,5.35 -7.85,5.35 -7.85,-5.35
3D body: height 1.32, standoff 1.14, extent 2,-2.155 5.6,-1.655
3D body: height 2.52, standoff 1.32, extent 3.6,-2.155 3.625,-1.655
3D body: height 1.32, standoff 1.14, extent 2,-0.885 5.6,-0.385
3D body: height 2.52, standoff 1.32, extent 3.6,-0.885 3.625,-0.385
3D body: height 1.32, standoff 0, extent -5.8,-4.695 -5.6,-4.195
3D body: height 0.18, standoff 0, extent -7.4,-3.425 -5.8,-2.925
3D body: height 1.32, standoff 0, extent -5.8,-3.425 -5.6,-2.925
3D body: height 0.18, standoff 0, extent -7.4,-4.695 -5.8,-4.195
3D body: height 2.52, standoff 1.32, extent -3.625,-4.695 -3.6,-4.195
3D body: height 2.52, standoff 1.32, extent -3.625,-3.425 -3.6,-2.925
3D body: height 1.32, standoff 1.14, extent -5.6,0.385 -2,0.885
3D body: height 1.32, standoff 1.14, extent -5.6,1.655 -2,2.155
3D body: height 2.52, standoff 1.32, extent -3.625,1.655 -3.6,2.155
3D body: height 1.32, standoff 1.14, extent -5.6,-0.885 -2,-0.385
3D body: height 0.18, standoff 0, extent -7.4,1.655 -5.8,2.155
3D body: height 0.18, standoff 0, extent -7.4,2.925 -5.8,3.425
3D body: height 1.32, standoff 0, extent -5.8,4.195 -5.6,4.695
3D body: height 0.18, standoff 0, extent -7.4,4.195 -5.8,4.695
3D body: height 0.18, standoff 0, extent -7.4,-0.885 -5.8,-0.385
3D body: height 2.52, standoff 1.32, extent -3.625,-0.885 -3.6,-0.385
3D body: height 0.18, standoff 0, extent -7.4,0.385 -5.8,0.885
3D body: height 2.52, standoff 1.32, extent -3.625,0.385 -3.6,0.885
3D body: height 1.32, standoff 0, extent 5.6,1.655 5.8,2.155
3D body: height 2.52, standoff 1.32, extent 3.6,1.655 3.625,2.155
3D body: height 1.32, standoff 0, extent 5.6,2.925 5.8,3.425
3D body: height 2.52, standoff 1.32, extent 3.6,2.925 3.625,3.425
3D body: height 0.18, standoff 0, extent 5.8,1.655 7.4,2.155
3D body: height 0.18, standoff 0, extent 5.8,2.925 7.4,3.425
3D body: height 0.18, standoff 0, extent 5.8,4.195 7.4,4.695
3D body: height 2.89, standoff 2.88, extent -3,4 -2.5,4.5
3D body: height 1.32, standoff 0, extent 5.6,4.195 5.8,4.695
3D body: height 1.32, standoff 1.14, extent 2,4.195 5.6,4.695
3D body: height 2.52, standoff 1.32, extent 3.6,4.195 3.625,4.695
3D body: height 1.32, standoff 1.14, extent -5.6,4.195 -2,4.695
3D body: height 2.88, standoff 2.52, extent -3.25,-4.75 3.25,4.75
3D body: height 1.32, standoff 0, extent -1.8,-5.1 1.8,5.1
3D body: height 2.52, standoff 1.32, extent -3.6,-5.1 3.6,5.1
3D body: height 1.32, standoff 1.14, extent 2,0.385 5.6,0.885
3D body: height 1.32, standoff 1.14, extent 2,1.655 5.6,2.155
3D body: height 1.32, standoff 1.14, extent 2,2.925 5.6,3.425
3D body: height 1.32, standoff 1.14, extent -5.6,-4.695 -2,-4.195
3D body: height 1.32, standoff 1.14, extent -5.6,-3.425 -2,-2.925
3D body: height 1.32, standoff 1.14, extent -5.6,-2.155 -2,-1.655
3D body: height 1.32, standoff 1.14, extent -5.6,2.925 -2,3.425
3D body: height 2.52, standoff 1.32, extent -3.625,2.925 -3.6,3.425
3D body: height 2.52, standoff 1.32, extent -3.625,4.195 -3.6,4.695
3D body: height 0.18, standoff 0, extent -7.4,-2.155 -5.8,-1.655
3D body: height 1.32, standoff 0, extent -5.8,-2.155 -5.6,-1.655
3D body: height 2.52, standoff 1.32, extent -3.625,-2.155 -3.6,-1.655
3D body: height 1.32, standoff 0, extent -5.8,-0.885 -5.6,-0.385
3D body: height 1.32, standoff 0, extent -5.8,0.385 -5.6,0.885
3D body: height 1.32, standoff 0, extent -5.8,1.655 -5.6,2.155
3D body: height 1.32, standoff 0, extent -5.8,2.925 -5.6,3.425
3D body: height 1.32, standoff 0, extent 5.6,-3.425 5.8,-2.925
3D body: height 1.32, standoff 0, extent 5.6,-2.155 5.8,-1.655
3D body: height 1.32, standoff 0, extent 5.6,-0.885 5.8,-0.385
3D body: height 1.32, standoff 0, extent 5.6,-4.695 5.8,-4.195
3D body: height 1.32, standoff 1.14, extent 2,-4.695 5.6,-4.195
3D body: height 2.52, standoff 1.32, extent 3.6,-4.695 3.625,-4.195
3D body: height 1.32, standoff 1.14, extent 2,-3.425 5.6,-2.925
3D body: height 2.52, standoff 1.32, extent 3.6,-3.425 3.625,-2.925
3D body: height 0.18, standoff 0, extent 5.8,0.385 7.4,0.885
3D body: height 1.32, standoff 0, extent 5.6,0.385 5.8,0.885
3D body: height 2.52, standoff 1.32, extent 3.6,0.385 3.625,0.885
3D body: height 0.18, standoff 0, extent 5.8,-4.695 7.4,-4.195
3D body: height 0.18, standoff 0, extent 5.8,-3.425 7.4,-2.925
3D body: height 0.18, standoff 0, extent 5.8,-2.155 7.4,-1.655
3D body: height 0.18, standoff 0, extent 5.8,-0.885 7.4,-0.385

## ICC_TDFN6-EPAD_2X1P3_P040_H0P6 [mm] "MCD-03371"
height 0.6
pads (7):
  rect 0.6x0.25 smd mask+0.035: 1(-1.025,0.4) 2(-1.025,0) 3(-1.025,-0.4) 4(1.025,-0.4) 5(1.025,0) 6(1.025,0.4)
  rect 1.05x1.25 smd mask+0.05: EPAD(0,0)
Top Overlay:
  lines w0.12: -1.15,0.675 -1.15,0.825 -1,0.825
M14-Top Assembly:
  lines w0.01: -1.025,-0.675 -1.025,0.675 1.025,0.675 1.025,-0.675 -1.025,-0.675 ; -1.025,-0.525 -0.725,-0.525 -0.725,-0.275 -1.025,-0.275 -1.025,-0.525 ; -1.025,-0.125 -0.725,-0.125 -0.725,0.125 -1.025,0.125 -1.025,-0.125 ; -1.025,0.275 -0.725,0.275 -0.725,0.525 -1.025,0.525 -1.025,0.275 ; -0.55,-0.45 0.55,-0.45 0.55,0.45 -0.375,0.45 -0.55,0.275 -0.55,-0.45 ; 0.725,-0.525 0.725,-0.275 1.025,-0.275 1.025,-0.525 0.725,-0.525 ; 0.725,-0.125 0.725,0.125 1.025,0.125 1.025,-0.125 0.725,-0.125 ; 0.725,0.275 0.725,0.525 1.025,0.525 1.025,0.275 0.725,0.275
  text "1" at -0.922,0.275 h0.4
  text "4" at 0.787,-0.525 h0.4
  text "6" at 0.791,0.279 h0.4
  text "EP" at -0.216,-0.125 h0.4
  text "'.Designator'" at -2,-0.25 h0.75
  text "3" at -0.958,-0.521 h0.4
M16-Top Courtyard:
  lines w0.01: -1.45,-0.875 1.45,-0.875 1.45,0.875 -1.45,0.875 -1.45,-0.875
3D body: height 0.6, standoff 0, extent -1.025,-0.675 1.025,0.675
3D body: height 0.61, standoff 0.6, extent -0.974,0.425 -0.775,0.625

## ICC_TFBGA25_5X5-BALL-ARRAY_6X8_P1 [mm] "IPC"
height 1.2
pads (25):
  round 0.35 smd mask+0.05: A1(-2,2) A2(-1,2) A3(0,2) A4(1,2) A5(2,2) B1(-2,1) B2(-1,1) B3(0,1) B4(1,1) B5(2,1) C1(-2,0) C2(-1,0) C3(0,0) C4(1,0) C5(2,0) D1(-2,-1) D2(-1,-1) D3(0,-1) D4(1,-1) D5(2,-1) E1(-2,-2) E2(-1,-2) E3(0,-2) E4(1,-2) E5(2,-2)
Top Overlay:
  circle w0.12: c-2.55,3.55 r0.3
  lines w0.12: -3.15,3.125 -3.15,4.15 -2.125,4.15 ; -3.05,3.125 -3.175,3.125 -3.175,4.175 -2.125,4.175 -2.125,4.05 ; -3.05,-4.05 -3.05,4.05 3.05,4.05 3.05,-4.05 -3.05,-4.05
  text "A1" at -2.625,2.275 h1.3
M14-Top Assembly:
  circle w0.01: c-2,-2 r0.225
  circle w0.01: c-1,-2 r0.225
  circle w0.01: c0,-2 r0.225
  circle w0.01: c1,-2 r0.225
  circle w0.01: c2,-2 r0.225
  circle w0.01: c-2,-1 r0.225
  circle w0.01: c-1,-1 r0.225
  circle w0.01: c0,-1 r0.225
  circle w0.01: c1,-1 r0.225
  circle w0.01: c2,-1 r0.225
  circle w0.01: c-2,0 r0.225
  circle w0.01: c-1,0 r0.225
  circle w0.01: c0,0 r0.225
  circle w0.01: c1,0 r0.225
  circle w0.01: c2,0 r0.225
  circle w0.01: c-2,1 r0.225
  circle w0.01: c-1,1 r0.225
  circle w0.01: c0,1 r0.225
  circle w0.01: c1,1 r0.225
  circle w0.01: c2,1 r0.225
  circle w0.01: c2,2 r0.225
  circle w0.01: c1,2 r0.225
  circle w0.01: c0,2 r0.225
  circle w0.01: c-1,2 r0.225
  circle w0.01: c-2,2 r0.225
  circle w0.01: c-2.55,3.55 r0.325
  lines w0.01: -3.05,-4.05 3.05,-4.05 3.05,4.05 -3.05,4.05 -3.05,-4.05
  text "A1" at -2.35,1.775 h0.75
  text "'.Designator'" at -2,0 h0.75
M16-Top Courtyard:
  lines w0.01: -3.3,-4.3 3.3,-4.3 3.3,4.3 -3.3,4.3 -3.3,-4.3
3D body: height 0.36, standoff -0.04, extent 1.801,-2.197 2.2,-1.803
3D body: height 0.36, standoff -0.04, extent 0.801,-2.197 1.2,-1.803
3D body: height 0.36, standoff -0.04, extent -0.199,-2.197 0.2,-1.803
3D body: height 0.36, standoff -0.04, extent -1.199,-2.197 -0.8,-1.803
3D body: height 0.36, standoff -0.04, extent -2.199,-2.197 -1.8,-1.803
3D body: height 0.36, standoff -0.04, extent 1.801,-1.197 2.2,-0.803
3D body: height 0.36, standoff -0.04, extent 0.801,-1.197 1.2,-0.803
3D body: height 0.36, standoff -0.04, extent -0.199,-1.197 0.2,-0.803
3D body: height 0.36, standoff -0.04, extent -1.199,-1.197 -0.8,-0.803
3D body: height 0.36, standoff -0.04, extent -2.199,-1.197 -1.8,-0.803
3D body: height 0.36, standoff -0.04, extent 1.801,-0.197 2.2,0.197
3D body: height 0.36, standoff -0.04, extent 0.801,-0.197 1.2,0.197
3D body: height 0.36, standoff -0.04, extent -0.199,-0.197 0.2,0.197
3D body: height 0.36, standoff -0.04, extent -1.199,-0.197 -0.8,0.197
3D body: height 0.36, standoff -0.04, extent -2.199,-0.197 -1.8,0.197
3D body: height 0.36, standoff -0.04, extent 1.801,0.803 2.2,1.197
3D body: height 0.36, standoff -0.04, extent 0.801,0.803 1.2,1.197
3D body: height 0.36, standoff -0.04, extent -0.199,0.803 0.2,1.197
3D body: height 0.36, standoff -0.04, extent -1.199,0.803 -0.8,1.197
3D body: height 0.36, standoff -0.04, extent -2.199,0.803 -1.8,1.197
3D body: height 0.36, standoff -0.04, extent 1.801,1.803 2.2,2.197
3D body: height 0.36, standoff -0.04, extent 0.801,1.803 1.2,2.197
3D body: height 0.36, standoff -0.04, extent -0.199,1.803 0.2,2.197
3D body: height 0.36, standoff -0.04, extent -1.199,1.803 -0.8,2.197
3D body: height 0.36, standoff -0.04, extent -2.199,1.803 -1.8,2.197
3D body: height 1.2, standoff 0.3, extent -3.055,-4.055 3.055,4.055
3D body: height 1.21, standoff 1.2, extent -2.623,3.026 -2.025,3.625

## ICC_TFBGA48_6X8_P075 [mm] "MCD-01688"
height 1.2
pads (48):
  round 0.32 smd mask+0.05: A1(-1.875,2.625) A2(-1.125,2.625) A3(-0.375,2.625) A4(0.375,2.625) A5(1.125,2.625) A6(1.875,2.625) B1(-1.875,1.875) B2(-1.125,1.875) B3(-0.375,1.875) B4(0.375,1.875) B5(1.125,1.875) B6(1.875,1.875) C1(-1.875,1.125) C2(-1.125,1.125) C3(-0.375,1.125) C4(0.375,1.125) C5(1.125,1.125) C6(1.875,1.125) D1(-1.875,0.375) D2(-1.125,0.375) D3(-0.375,0.375) D4(0.375,0.375) D5(1.125,0.375) D6(1.875,0.375) E1(-1.875,-0.375) E2(-1.125,-0.375) E3(-0.375,-0.375) E4(0.375,-0.375) E5(1.125,-0.375) E6(1.875,-0.375) F1(-1.875,-1.125) F2(-1.125,-1.125) F3(-0.375,-1.125) F4(0.375,-1.125) F5(1.125,-1.125) F6(1.875,-1.125) G1(-1.875,-1.875) G2(-1.125,-1.875) G3(-0.375,-1.875) G4(0.375,-1.875) G5(1.125,-1.875) G6(1.875,-1.875) H1(-1.875,-2.625) H2(-1.125,-2.625) H3(-0.375,-2.625) H4(0.375,-2.625) H5(1.125,-2.625) H6(1.875,-2.625)
Top Overlay:
  circle w0.12: c-2.5,3.5 r0.3
  lines w0.12: -3.175,3.125 -3.175,4.175 -2.125,4.175 ; -3.05,-4.05 -3.05,4.05 3.05,4.05 3.05,-4.05 -3.05,-4.05
M14-Top Assembly:
  circle w0.01: c-1.875,-2.625 r0.2
  circle w0.01: c-1.125,-2.625 r0.2
  circle w0.01: c-0.375,-2.625 r0.2
  circle w0.01: c0.375,-2.625 r0.2
  circle w0.01: c1.125,-2.625 r0.2
  circle w0.01: c1.875,-2.625 r0.2
  circle w0.01: c-1.875,-1.875 r0.2
  circle w0.01: c-1.125,-1.875 r0.2
  circle w0.01: c-0.375,-1.875 r0.2
  circle w0.01: c0.375,-1.875 r0.2
  circle w0.01: c1.125,-1.875 r0.2
  circle w0.01: c1.875,-1.875 r0.2
  circle w0.01: c-1.875,-1.125 r0.2
  circle w0.01: c-1.125,-1.125 r0.2
  circle w0.01: c-0.375,-1.125 r0.2
  circle w0.01: c0.375,-1.125 r0.2
  circle w0.01: c1.125,-1.125 r0.2
  circle w0.01: c1.875,-1.125 r0.2
  circle w0.01: c-1.875,-0.375 r0.2
  circle w0.01: c-1.125,-0.375 r0.2
  circle w0.01: c-0.375,-0.375 r0.2
  circle w0.01: c0.375,-0.375 r0.2
  circle w0.01: c1.125,-0.375 r0.2
  circle w0.01: c1.875,-0.375 r0.2
  circle w0.01: c-1.875,0.375 r0.2
  circle w0.01: c-1.125,0.375 r0.2
  circle w0.01: c-0.375,0.375 r0.2
  circle w0.01: c0.375,0.375 r0.2
  circle w0.01: c1.125,0.375 r0.2
  circle w0.01: c1.875,0.375 r0.2
  circle w0.01: c-1.875,1.125 r0.2
  circle w0.01: c-1.125,1.125 r0.2
  circle w0.01: c-0.375,1.125 r0.2
  circle w0.01: c0.375,1.125 r0.2
  circle w0.01: c1.125,1.125 r0.2
  circle w0.01: c1.875,1.125 r0.2
  circle w0.01: c-1.875,1.875 r0.2
  circle w0.01: c-1.125,1.875 r0.2
  circle w0.01: c-0.375,1.875 r0.2
  circle w0.01: c0.375,1.875 r0.2
  circle w0.01: c1.125,1.875 r0.2
  circle w0.01: c1.875,1.875 r0.2
  circle w0.01: c1.875,2.625 r0.2
  circle w0.01: c1.125,2.625 r0.2
  circle w0.01: c0.375,2.625 r0.2
  circle w0.01: c-0.375,2.625 r0.2
  circle w0.01: c-1.125,2.625 r0.2
  circle w0.01: c-1.875,2.625 r0.2
  circle w0.01: c-2.5,3.5 r0.3
  lines w0.01: -3.05,-4.05 -3.05,4.05 3.05,4.05 3.05,-4.05 -3.05,-4.05
  text "A1" at -2.125,2.425 h0.4
  text "'.Designator'" at -2,-0.5 h0.75
M16-Top Courtyard:
  lines w0.01: -3.25,-4.25 -3.25,4.25 -3.05,4.25 3.25,4.25 3.25,-4.25 -3.25,-4.25
3D body: height 1.2, standoff 0.3, extent -3.05,-4.05 3.05,4.05
3D body: height 0.36, standoff -0.04, extent -2.074,-2.072 -1.675,-1.678
3D body: height 0.36, standoff -0.04, extent -1.324,-2.072 -0.925,-1.678
3D body: height 0.36, standoff -0.04, extent -0.574,-2.072 -0.175,-1.678
3D body: height 0.36, standoff -0.04, extent 0.176,-2.072 0.575,-1.678
3D body: height 0.36, standoff -0.04, extent 0.926,-2.072 1.325,-1.678
3D body: height 0.36, standoff -0.04, extent 1.676,-2.072 2.075,-1.678
3D body: height 0.36, standoff -0.04, extent -2.074,-2.822 -1.675,-2.428
3D body: height 0.36, standoff -0.04, extent -1.324,-2.822 -0.925,-2.428
3D body: height 0.36, standoff -0.04, extent -0.574,-2.822 -0.175,-2.428
3D body: height 0.36, standoff -0.04, extent 0.176,-2.822 0.575,-2.428
3D body: height 0.36, standoff -0.04, extent 0.926,-2.822 1.325,-2.428
3D body: height 0.36, standoff -0.04, extent 1.676,-2.822 2.075,-2.428
3D body: height 0.36, standoff -0.04, extent -2.074,-0.572 -1.675,-0.178
3D body: height 0.36, standoff -0.04, extent -1.324,-0.572 -0.925,-0.178
3D body: height 0.36, standoff -0.04, extent -0.574,-0.572 -0.175,-0.178
3D body: height 0.36, standoff -0.04, extent 0.176,-0.572 0.575,-0.178
3D body: height 0.36, standoff -0.04, extent 0.926,-0.572 1.325,-0.178
3D body: height 0.36, standoff -0.04, extent 1.676,-0.572 2.075,-0.178
3D body: height 0.36, standoff -0.04, extent -2.074,-1.322 -1.675,-0.928
3D body: height 0.36, standoff -0.04, extent -1.324,-1.322 -0.925,-0.928
3D body: height 0.36, standoff -0.04, extent -0.574,-1.322 -0.175,-0.928
3D body: height 0.36, standoff -0.04, extent 0.176,-1.322 0.575,-0.928
3D body: height 0.36, standoff -0.04, extent 0.926,-1.322 1.325,-0.928
3D body: height 0.36, standoff -0.04, extent 1.676,-1.322 2.075,-0.928
3D body: height 0.36, standoff -0.04, extent -2.074,0.928 -1.675,1.322
3D body: height 0.36, standoff -0.04, extent -1.324,0.928 -0.925,1.322
3D body: height 0.36, standoff -0.04, extent -0.574,0.928 -0.175,1.322
3D body: height 0.36, standoff -0.04, extent 0.176,0.928 0.575,1.322
3D body: height 0.36, standoff -0.04, extent 0.926,0.928 1.325,1.322
3D body: height 0.36, standoff -0.04, extent 1.676,0.928 2.075,1.322
3D body: height 0.36, standoff -0.04, extent -2.074,0.178 -1.675,0.572
3D body: height 0.36, standoff -0.04, extent -1.324,0.178 -0.925,0.572
3D body: height 0.36, standoff -0.04, extent -0.574,0.178 -0.175,0.572
3D body: height 0.36, standoff -0.04, extent 0.176,0.178 0.575,0.572
3D body: height 0.36, standoff -0.04, extent 0.926,0.178 1.325,0.572
3D body: height 0.36, standoff -0.04, extent 1.676,0.178 2.075,0.572
3D body: height 0.36, standoff -0.04, extent 1.676,1.678 2.075,2.072
3D body: height 0.36, standoff -0.04, extent 0.926,1.678 1.325,2.072
3D body: height 0.36, standoff -0.04, extent 0.176,1.678 0.575,2.072
3D body: height 0.36, standoff -0.04, extent -0.574,1.678 -0.175,2.072
3D body: height 0.36, standoff -0.04, extent -1.324,1.678 -0.925,2.072
3D body: height 0.36, standoff -0.04, extent -2.074,1.678 -1.675,2.072
3D body: height 0.36, standoff -0.04, extent 1.676,2.428 2.075,2.822
3D body: height 0.36, standoff -0.04, extent 0.926,2.428 1.325,2.822
3D body: height 0.36, standoff -0.04, extent 0.176,2.428 0.575,2.822
3D body: height 0.36, standoff -0.04, extent -0.574,2.428 -0.175,2.822
3D body: height 0.36, standoff -0.04, extent -1.324,2.428 -0.925,2.822
3D body: height 1.21, standoff 1.2, extent -2.797,3.201 -2.2,3.8
3D body: height 0.36, standoff -0.04, extent -2.074,2.428 -1.675,2.822

## ICC_TFBGA54_3X9-BALL-X2_8X8_P080 [mm] "IPC"
height 1.2
pads (54):
  round 0.35 smd mask+0.05: A1(-3.2,3.2) A2(-2.4,3.2) A3(-1.6,3.2) A7(1.6,3.2) A8(2.4,3.2) A9(3.2,3.2) B1(-3.2,2.4) B2(-2.4,2.4) B3(-1.6,2.4) B7(1.6,2.4) B8(2.4,2.4) B9(3.2,2.4) C1(-3.2,1.6) C2(-2.4,1.6) C3(-1.6,1.6) C7(1.6,1.6) C8(2.4,1.6) C9(3.2,1.6) D1(-3.2,0.8) D2(-2.4,0.8) D3(-1.6,0.8) D7(1.6,0.8) D8(2.4,0.8) D9(3.2,0.8) E1(-3.2,0) E2(-2.4,0) E3(-1.6,0) E7(1.6,0) E8(2.4,0) E9(3.2,0) F1(-3.2,-0.8) F2(-2.4,-0.8) F3(-1.6,-0.8) F7(1.6,-0.8) F8(2.4,-0.8) F9(3.2,-0.8) G1(-3.2,-1.6) G2(-2.4,-1.6) G3(-1.6,-1.6) G7(1.6,-1.6) G8(2.4,-1.6) G9(3.2,-1.6) H1(-3.2,-2.4) H2(-2.4,-2.4) H3(-1.6,-2.4) H7(1.6,-2.4) H8(2.4,-2.4) H9(3.2,-2.4) J1(-3.2,-3.2) J2(-2.4,-3.2) J3(-1.6,-3.2) J7(1.6,-3.2) J8(2.4,-3.2) J9(3.2,-3.2)
Top Overlay:
  lines w0.12: -4.05,3.375 -4.05,3.4 -3.4,4.05 ; -4.6,3 -4.2,3 -4.4,3.4 -4.6,3 ; -4.05,-4.05 -4.05,4.05 4.05,4.05 4.05,-4.05 -4.05,-4.05
M14-Top Assembly:
  circle w0.01: c-3.2,-3.2 r0.225
  circle w0.01: c-2.4,-3.2 r0.225
  circle w0.01: c-1.6,-3.2 r0.225
  circle w0.01: c1.6,-3.2 r0.225
  circle w0.01: c2.4,-3.2 r0.225
  circle w0.01: c3.2,-3.2 r0.225
  circle w0.01: c-3.2,-2.4 r0.225
  circle w0.01: c-2.4,-2.4 r0.225
  circle w0.01: c-1.6,-2.4 r0.225
  circle w0.01: c1.6,-2.4 r0.225
  circle w0.01: c2.4,-2.4 r0.225
  circle w0.01: c3.2,-2.4 r0.225
  circle w0.01: c-3.2,-1.6 r0.225
  circle w0.01: c-2.4,-1.6 r0.225
  circle w0.01: c-1.6,-1.6 r0.225
  circle w0.01: c1.6,-1.6 r0.225
  circle w0.01: c2.4,-1.6 r0.225
  circle w0.01: c3.2,-1.6 r0.225
  circle w0.01: c-3.2,-0.8 r0.225
  circle w0.01: c-2.4,-0.8 r0.225
  circle w0.01: c-1.6,-0.8 r0.225
  circle w0.01: c1.6,-0.8 r0.225
  circle w0.01: c2.4,-0.8 r0.225
  circle w0.01: c3.2,-0.8 r0.225
  circle w0.01: c-3.2,0 r0.225
  circle w0.01: c-2.4,0 r0.225
  circle w0.01: c-1.6,0 r0.225
  circle w0.01: c1.6,0 r0.225
  circle w0.01: c2.4,0 r0.225
  circle w0.01: c3.2,0 r0.225
  circle w0.01: c-3.2,0.8 r0.225
  circle w0.01: c-2.4,0.8 r0.225
  circle w0.01: c-1.6,0.8 r0.225
  circle w0.01: c1.6,0.8 r0.225
  circle w0.01: c2.4,0.8 r0.225
  circle w0.01: c3.2,0.8 r0.225
  circle w0.01: c-3.2,1.6 r0.225
  circle w0.01: c-2.4,1.6 r0.225
  circle w0.01: c-1.6,1.6 r0.225
  circle w0.01: c1.6,1.6 r0.225
  circle w0.01: c2.4,1.6 r0.225
  circle w0.01: c3.2,1.6 r0.225
  circle w0.01: c-3.2,2.4 r0.225
  circle w0.01: c-2.4,2.4 r0.225
  circle w0.01: c-1.6,2.4 r0.225
  circle w0.01: c1.6,2.4 r0.225
  circle w0.01: c2.4,2.4 r0.225
  circle w0.01: c3.2,2.4 r0.225
  circle w0.01: c-3.2,3.2 r0.225
  circle w0.01: c-2.4,3.2 r0.225
  circle w0.01: c-1.6,3.2 r0.225
  circle w0.01: c1.6,3.2 r0.225
  circle w0.01: c2.4,3.2 r0.225
  circle w0.01: c3.2,3.2 r0.225
  region: -4.05,4.05 -4.05,3.425 -3.425,4.05
  lines w0.01: -4.05,-4.05 4.05,-4.05 4.05,4.05 -4.05,4.05 -4.05,-4.05
  text "'.Designator'" at -2,-0.5 h0.75
  text "E" at -4,-0.2 h0.7
  text "D" at -4,0.6 h0.7
  text "C" at -4,1.4 h0.7
  text "B" at -4,2.2 h0.7
  text "A" at -4,3 h0.7
  text "F" at -4,-1 h0.7
  text "G" at -4,-1.8 h0.7
  text "H" at -4,-2.6 h0.7
  text "J" at -4,-3.4 h0.7
  text "1" at -3.3,3.5 h0.7
  text "2" at -2.55,3.5 h0.7
  text "3" at -1.75,3.5 h0.7
  text "9" at 3.05,3.5 h0.7
  text "8" at 2.25,3.5 h0.7
  text "7" at 1.45,3.5 h0.7
M16-Top Courtyard:
  lines w0.01: -4.3,-4.3 -4.3,-3.8 -4.3,4.3 4.3,4.3 4.3,-4.3 -4.3,-4.3
3D body: height 0.36, standoff -0.04, extent 1.401,-3.397 1.8,-3.003
3D body: height 0.36, standoff -0.04, extent 2.201,-3.397 2.6,-3.003
3D body: height 0.36, standoff -0.04, extent 3.001,-3.397 3.4,-3.003
3D body: height 0.36, standoff -0.04, extent -1.799,-3.397 -1.4,-3.003
3D body: height 0.36, standoff -0.04, extent -2.599,-3.397 -2.2,-3.003
3D body: height 0.36, standoff -0.04, extent -3.399,-3.397 -3,-3.003
3D body: height 0.36, standoff -0.04, extent 1.401,-2.597 1.8,-2.203
3D body: height 0.36, standoff -0.04, extent 2.201,-2.597 2.6,-2.203
3D body: height 0.36, standoff -0.04, extent 3.001,-2.597 3.4,-2.203
3D body: height 0.36, standoff -0.04, extent -1.799,-2.597 -1.4,-2.203
3D body: height 0.36, standoff -0.04, extent -2.599,-2.597 -2.2,-2.203
3D body: height 0.36, standoff -0.04, extent -3.399,-2.597 -3,-2.203
3D body: height 0.36, standoff -0.04, extent 1.401,-1.797 1.8,-1.403
3D body: height 0.36, standoff -0.04, extent 2.201,-1.797 2.6,-1.403
3D body: height 0.36, standoff -0.04, extent 3.001,-1.797 3.4,-1.403
3D body: height 0.36, standoff -0.04, extent -1.799,-1.797 -1.4,-1.403
3D body: height 0.36, standoff -0.04, extent -2.599,-1.797 -2.2,-1.403
3D body: height 0.36, standoff -0.04, extent -3.399,-1.797 -3,-1.403
3D body: height 0.36, standoff -0.04, extent 1.401,-0.997 1.8,-0.603
3D body: height 0.36, standoff -0.04, extent 2.201,-0.997 2.6,-0.603
3D body: height 0.36, standoff -0.04, extent 3.001,-0.997 3.4,-0.603
3D body: height 0.36, standoff -0.04, extent -1.799,-0.997 -1.4,-0.603
3D body: height 0.36, standoff -0.04, extent -2.599,-0.997 -2.2,-0.603
3D body: height 0.36, standoff -0.04, extent -3.399,-0.997 -3,-0.603
3D body: height 0.36, standoff -0.04, extent 1.401,-0.197 1.8,0.197
3D body: height 0.36, standoff -0.04, extent 2.201,-0.197 2.6,0.197
3D body: height 0.36, standoff -0.04, extent 3.001,-0.197 3.4,0.197
3D body: height 0.36, standoff -0.04, extent -1.799,-0.197 -1.4,0.197
3D body: height 0.36, standoff -0.04, extent -2.599,-0.197 -2.2,0.197
3D body: height 0.36, standoff -0.04, extent -3.399,-0.197 -3,0.197
3D body: height 0.36, standoff -0.04, extent 1.401,0.603 1.8,0.997
3D body: height 0.36, standoff -0.04, extent 2.201,0.603 2.6,0.997
3D body: height 0.36, standoff -0.04, extent 3.001,0.603 3.4,0.997
3D body: height 0.36, standoff -0.04, extent -1.799,0.603 -1.4,0.997
3D body: height 0.36, standoff -0.04, extent -2.599,0.603 -2.2,0.997
3D body: height 0.36, standoff -0.04, extent -3.399,0.603 -3,0.997
3D body: height 0.36, standoff -0.04, extent 1.401,1.403 1.8,1.797
3D body: height 0.36, standoff -0.04, extent 2.201,1.403 2.6,1.797
3D body: height 0.36, standoff -0.04, extent 3.001,1.403 3.4,1.797
3D body: height 0.36, standoff -0.04, extent -1.799,1.403 -1.4,1.797
3D body: height 0.36, standoff -0.04, extent -2.599,1.403 -2.2,1.797
3D body: height 0.36, standoff -0.04, extent -3.399,1.403 -3,1.797
3D body: height 0.36, standoff -0.04, extent 1.401,2.203 1.8,2.597
3D body: height 0.36, standoff -0.04, extent 2.201,2.203 2.6,2.597
3D body: height 0.36, standoff -0.04, extent 3.001,2.203 3.4,2.597
3D body: height 0.36, standoff -0.04, extent -1.799,2.203 -1.4,2.597
3D body: height 0.36, standoff -0.04, extent -2.599,2.203 -2.2,2.597
3D body: height 0.36, standoff -0.04, extent -3.399,2.203 -3,2.597
3D body: height 0.36, standoff -0.04, extent 1.401,3.003 1.8,3.397
3D body: height 0.36, standoff -0.04, extent 2.201,3.003 2.6,3.397
3D body: height 0.36, standoff -0.04, extent 3.001,3.003 3.4,3.397
3D body: height 0.36, standoff -0.04, extent -1.799,3.003 -1.4,3.397
3D body: height 0.36, standoff -0.04, extent -2.599,3.003 -2.2,3.397
3D body: height 0.36, standoff -0.04, extent -3.399,3.003 -3,3.397
3D body: height 1.2, standoff 0.3, extent -4.05,-4.05 4.05,4.05
3D body: height 1.21, standoff 1.2, extent -3.498,2.901 -2.9,3.5

## ICC_TFBGA90_8X13_P080 [mm] "IPC"
height 1.2
pads (90):
  round 0.35 smd mask+0.05: A1(-3.2,5.6) A2(-2.4,5.6) A3(-1.6,5.6) A7(1.6,5.6) A8(2.4,5.6) A9(3.2,5.6) B1(-3.2,4.8) B2(-2.4,4.8) B3(-1.6,4.8) B7(1.6,4.8) B8(2.4,4.8) B9(3.2,4.8) C1(-3.2,4) C2(-2.4,4) C3(-1.6,4) C7(1.6,4) C8(2.4,4) C9(3.2,4) D1(-3.2,3.2) D2(-2.4,3.2) D3(-1.6,3.2) D7(1.6,3.2) D8(2.4,3.2) D9(3.2,3.2) E1(-3.2,2.4) E2(-2.4,2.4) E3(-1.6,2.4) E7(1.6,2.4) E8(2.4,2.4) E9(3.2,2.4) F1(-3.2,1.6) F2(-2.4,1.6) F3(-1.6,1.6) F7(1.6,1.6) F8(2.4,1.6) F9(3.2,1.6) G1(-3.2,0.8) G2(-2.4,0.8) G3(-1.6,0.8) G7(1.6,0.8) G8(2.4,0.8) G9(3.2,0.8) H1(-3.2,0) H2(-2.4,0) H3(-1.6,0) H7(1.6,0) H8(2.4,0) H9(3.2,0) J1(-3.2,-0.8) J2(-2.4,-0.8) J3(-1.6,-0.8) J7(1.6,-0.8) J8(2.4,-0.8) J9(3.2,-0.8) K1(-3.2,-1.6) K2(-2.4,-1.6) K3(-1.6,-1.6) K7(1.6,-1.6) K8(2.4,-1.6) K9(3.2,-1.6) L1(-3.2,-2.4) L2(-2.4,-2.4) L3(-1.6,-2.4) L7(1.6,-2.4) L8(2.4,-2.4) L9(3.2,-2.4) M1(-3.2,-3.2) M2(-2.4,-3.2) M3(-1.6,-3.2) M7(1.6,-3.2) M8(2.4,-3.2) M9(3.2,-3.2) N1(-3.2,-4) N2(-2.4,-4) N3(-1.6,-4) N7(1.6,-4) N8(2.4,-4) N9(3.2,-4) P1(-3.2,-4.8) P2(-2.4,-4.8) P3(-1.6,-4.8) P7(1.6,-4.8) P8(2.4,-4.8) P9(3.2,-4.8) R1(-3.2,-5.6) R2(-2.4,-5.6) R3(-1.6,-5.6) R7(1.6,-5.6) R8(2.4,-5.6) R9(3.2,-5.6)
Top Overlay:
  lines w0.12: -4.2,5.25 -4.2,6.7 -2.875,6.7 ; -2.851,5.623 ccw(c-3.2,5.6) -2.85,5.6 ; -4.05,-6.55 4.05,-6.55 4.05,6.55 -4.05,6.55 -4.05,-6.55
M14-Top Assembly:
  circle w0.01: c-3.2,5.6 r0.35
  circle w0.01: c-3.2,5.6 r0.225
  circle w0.01: c-2.4,5.6 r0.225
  circle w0.01: c-1.6,5.6 r0.225
  circle w0.01: c1.6,5.6 r0.225
  circle w0.01: c2.4,5.6 r0.225
  circle w0.01: c3.2,5.6 r0.225
  circle w0.01: c-3.2,-5.6 r0.225
  circle w0.01: c-2.4,-5.6 r0.225
  circle w0.01: c-1.6,-5.6 r0.225
  circle w0.01: c1.6,-5.6 r0.225
  circle w0.01: c2.4,-5.6 r0.225
  circle w0.01: c3.2,-5.6 r0.225
  circle w0.01: c3.2,-4.8 r0.225
  circle w0.01: c2.4,-4.8 r0.225
  circle w0.01: c1.6,-4.8 r0.225
  circle w0.01: c-1.6,-4.8 r0.225
  circle w0.01: c-2.4,-4.8 r0.225
  circle w0.01: c-3.2,-4.8 r0.225
  circle w0.01: c3.2,-4 r0.225
  circle w0.01: c2.4,-4 r0.225
  circle w0.01: c1.6,-4 r0.225
  circle w0.01: c-1.6,-4 r0.225
  circle w0.01: c-2.4,-4 r0.225
  circle w0.01: c-3.2,-4 r0.225
  circle w0.01: c3.2,-3.2 r0.225
  circle w0.01: c2.4,-3.2 r0.225
  circle w0.01: c1.6,-3.2 r0.225
  circle w0.01: c-1.6,-3.2 r0.225
  circle w0.01: c-2.4,-3.2 r0.225
  circle w0.01: c-3.2,-3.2 r0.225
  circle w0.01: c3.2,-2.4 r0.225
  circle w0.01: c2.4,-2.4 r0.225
  circle w0.01: c1.6,-2.4 r0.225
  circle w0.01: c-1.6,-2.4 r0.225
  circle w0.01: c-2.4,-2.4 r0.225
  circle w0.01: c-3.2,-2.4 r0.225
  circle w0.01: c3.2,-1.6 r0.225
  circle w0.01: c2.4,-1.6 r0.225
  circle w0.01: c1.6,-1.6 r0.225
  circle w0.01: c-1.6,-1.6 r0.225
  circle w0.01: c-2.4,-1.6 r0.225
  circle w0.01: c-3.2,-1.6 r0.225
  circle w0.01: c3.2,-0.8 r0.225
  circle w0.01: c2.4,-0.8 r0.225
  circle w0.01: c1.6,-0.8 r0.225
  circle w0.01: c-1.6,-0.8 r0.225
  circle w0.01: c-2.4,-0.8 r0.225
  circle w0.01: c-3.2,-0.8 r0.225
  circle w0.01: c3.2,0 r0.225
  circle w0.01: c2.4,0 r0.225
  circle w0.01: c1.6,0 r0.225
  circle w0.01: c-1.6,0 r0.225
  circle w0.01: c-2.4,0 r0.225
  circle w0.01: c-3.2,0 r0.225
  circle w0.01: c3.2,0.8 r0.225
  circle w0.01: c2.4,0.8 r0.225
  circle w0.01: c1.6,0.8 r0.225
  circle w0.01: c-1.6,0.8 r0.225
  circle w0.01: c-2.4,0.8 r0.225
  circle w0.01: c-3.2,0.8 r0.225
  circle w0.01: c3.2,1.6 r0.225
  circle w0.01: c2.4,1.6 r0.225
  circle w0.01: c1.6,1.6 r0.225
  circle w0.01: c-1.6,1.6 r0.225
  circle w0.01: c-2.4,1.6 r0.225
  circle w0.01: c-3.2,1.6 r0.225
  circle w0.01: c3.2,2.4 r0.225
  circle w0.01: c2.4,2.4 r0.225
  circle w0.01: c1.6,2.4 r0.225
  circle w0.01: c-1.6,2.4 r0.225
  circle w0.01: c-2.4,2.4 r0.225
  circle w0.01: c-3.2,2.4 r0.225
  circle w0.01: c3.2,3.2 r0.225
  circle w0.01: c2.4,3.2 r0.225
  circle w0.01: c1.6,3.2 r0.225
  circle w0.01: c-1.6,3.2 r0.225
  circle w0.01: c-2.4,3.2 r0.225
  circle w0.01: c-3.2,3.2 r0.225
  circle w0.01: c3.2,4 r0.225
  circle w0.01: c2.4,4 r0.225
  circle w0.01: c1.6,4 r0.225
  circle w0.01: c-1.6,4 r0.225
  circle w0.01: c-2.4,4 r0.225
  circle w0.01: c-3.2,4 r0.225
  circle w0.01: c3.2,4.8 r0.225
  circle w0.01: c2.4,4.8 r0.225
  circle w0.01: c1.6,4.8 r0.225
  circle w0.01: c-1.6,4.8 r0.225
  circle w0.01: c-2.4,4.8 r0.225
  circle w0.01: c-3.2,4.8 r0.225
  lines w0.01: -4.05,-6.55 4.05,-6.55 4.05,6.55 -4.05,6.55 -4.05,-6.55
  text "'.Designator'" at -2,-0.5 h0.75
  text "A1" at -3.575,5.4 h0.75
M16-Top Courtyard:
  lines w0.01: -4.3,-6.8 -3.075,-6.8 4.3,-6.8 4.3,6.8 -4.3,6.8 -4.3,-6.8
3D body "BGA90-8X13.STEP": height 0.98, standoff 0, extent -4,-6.5 4,6.5
3D body: height 1.21, standoff 1.2, extent -3.448,5.351 -2.95,5.85
3D body: height 1.2, standoff 0, extent -4.055,-6.55 4.055,6.55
